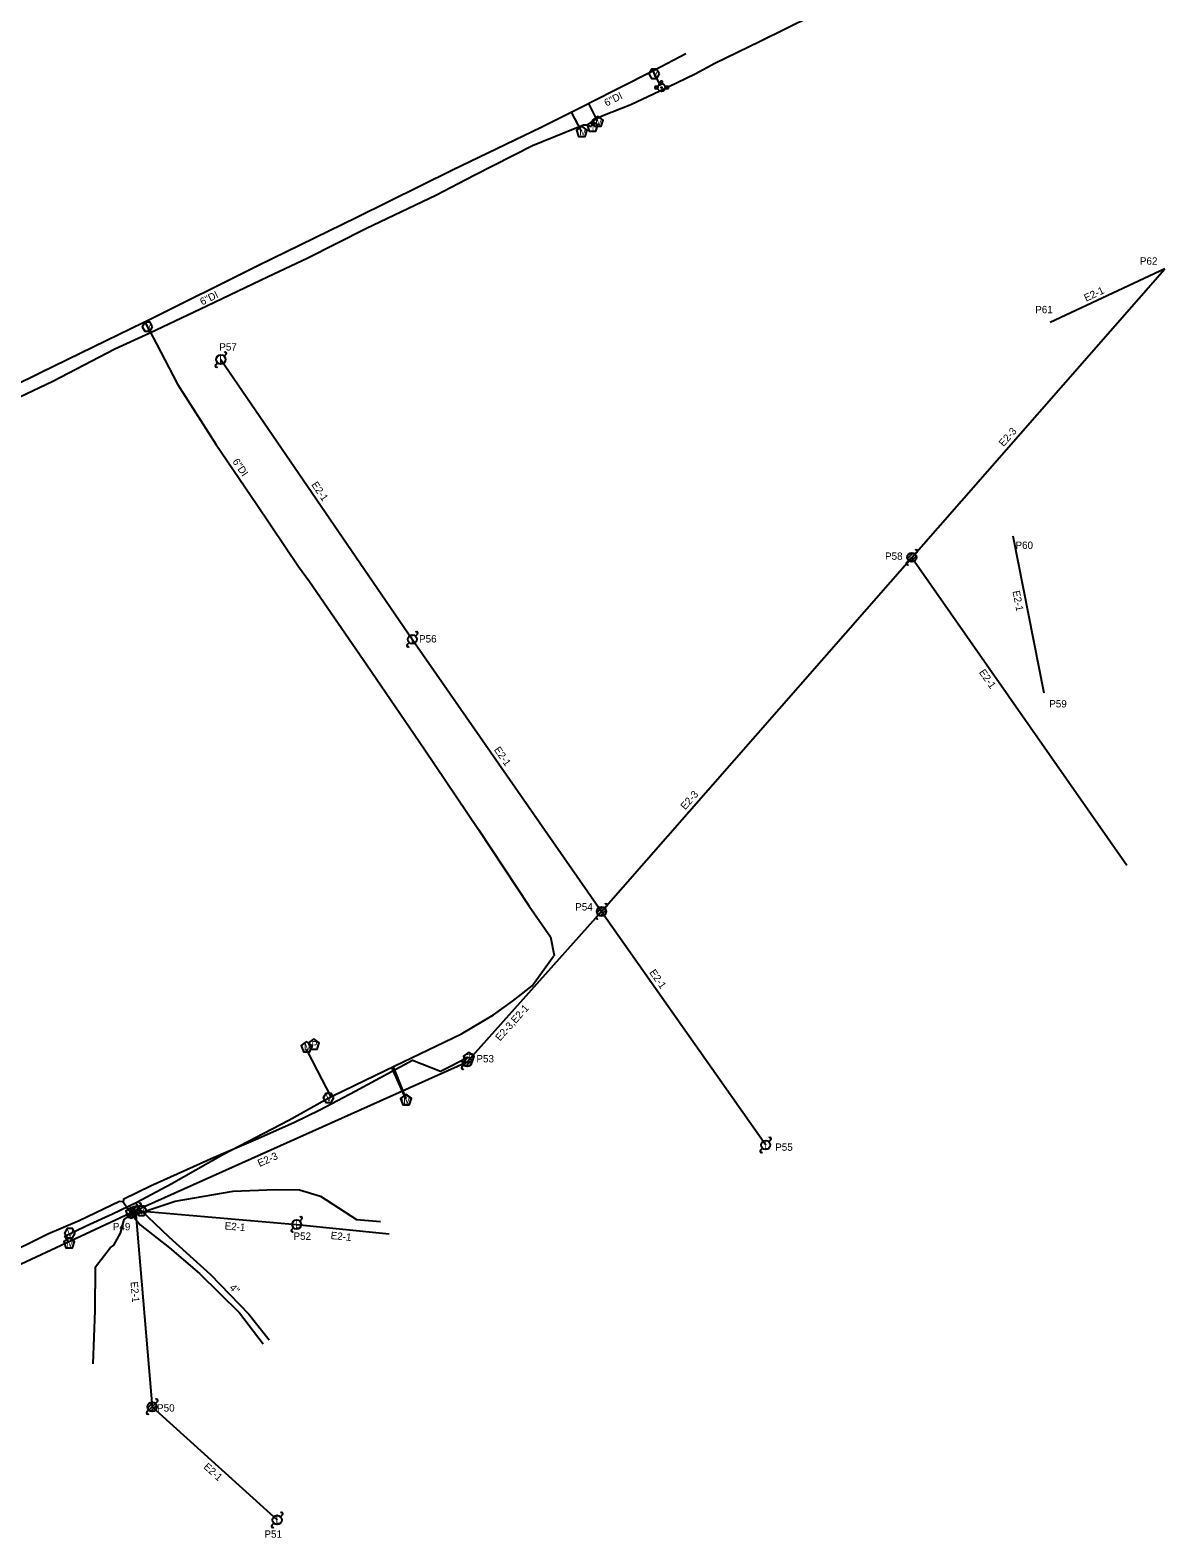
# Model space of a CAD drawing. Extents: x 1614474 to 1865144, y 1098877 to 1212550.
# Drawn here: x 1756944 to 1757561, y 1169162 to 1169980 of the extents above; entities that cross this region are included whole.
import ezdxf

# ---------------------------------------------------------------- set-up
doc = ezdxf.new("R2010")
doc.units = 0
for name, color, linetype in [('RD_EX_SU_H2O', 7, 'Continuous'), ('RD_EX_SU_Ovhd', 7, 'Continuous'), ('RD_EX_SU_Pole', 7, 'Continuous'), ('RD_EX_SU_Telecom', 7, 'Continuous'), ('RD_EX_SU_TX_H2O', 7, 'Continuous'), ('RD_EX_SU_TX_Pole', 7, 'Continuous')]:
    doc.layers.add(name, color=color, linetype=linetype)

# ---------------------------------------------------------------- blocks, each defined once
blk = doc.blocks.new('SUE_WM')
at = {"layer": 'RD_EX_SU_H2O'}
blk.add_lwpolyline([(0, 3.05), (-2.9, 0.94), (-1.79, -2.47), (1.79, -2.47), (2.9, 0.94)], close=True, dxfattribs=at)
blk.add_text('M', height=3.75, dxfattribs=at).set_placement((-1.43, -1.88))
blk = doc.blocks.new('SUE_WV')
at = {"layer": 'RD_EX_SU_H2O'}
blk.add_lwpolyline([(2.89, 0), (1.44, 2.5), (-1.44, 2.5), (-2.89, 0), (-1.44, -2.5), (1.44, -2.5)], close=True, dxfattribs=at)
blk.add_text('V', height=3.75, dxfattribs=at).set_placement((-1.43, -1.88))
blk = doc.blocks.new('SUE_TPP')
at = {"layer": 'RD_EX_SU_Telecom'}
blk.add_lwpolyline([(0, 3), (-2.85, 0.93), (-1.76, -2.43), (1.76, -2.43), (2.85, 0.93)], close=True, dxfattribs=at)
blk.add_text('T', height=3.75, dxfattribs=at).set_placement((-1.25, -1.88))

msp = doc.modelspace()

# ---------------------------------------------------------------- linework, layer by layer
at = {"layer": 'RD_EX_SU_H2O'}
for p, q in [((1757282.53, 1169958.35), (1757286.61, 1169950.33)), ((1757285.26, 1169949.92), (1757283.63, 1169949.92)), ((1757283.63, 1169949.92), (1757283.63, 1169948.87)), ((1757283.63, 1169948.87), (1757285.22, 1169948.87)), ((1757286.79, 1169952.7), (1757286.79, 1169951.36)), ((1757287.84, 1169952.7), (1757286.79, 1169952.7)), ((1757287.84, 1169951.34), (1757287.84, 1169952.7)), ((1757290.98, 1169949.92), (1757289.29, 1169949.92)), ((1757289.33, 1169948.87), (1757290.98, 1169948.87)), ((1757290.98, 1169948.87), (1757290.98, 1169949.92)), ((1757247.59, 1169940.71), (1757252.37, 1169931.3)), ((1757238.16, 1169935.97), (1757243.69, 1169925.62)), ((1757140.67, 1169417.32), (1757148.29, 1169400.22)), ((1757141.49, 1169417.71), (1757148.47, 1169400.5))]:
    msp.add_line(p, q, dxfattribs=at)
for points in [[(1756876.22, 1169758.33), (1756950.1, 1169794.65), (1756985.75, 1169811.98), (1757005.71, 1169821.7), (1757007.74, 1169822.73), (1757068.09, 1169852.64), (1757121.72, 1169879.04), (1757173.85, 1169904.73), (1757221.98, 1169927.84), (1757237.2, 1169935.44), (1757238.85, 1169936.36), (1757246.58, 1169940.19), (1757248.96, 1169941.41), (1757281.53, 1169957.91), (1757283.28, 1169958.73), (1757300.53, 1169967.83)], [(1757006.66, 1169822.19), (1757012.99, 1169810.13), (1757024.5, 1169788.2), (1757045.29, 1169755.66), (1757067.46, 1169722.91), (1757090.16, 1169689.33)], [(1757090.16, 1169689.33), (1757096.05, 1169681.09), (1757127.18, 1169635.98), (1757158.33, 1169590.22), (1757187.84, 1169546.51), (1757215.37, 1169504.84), (1757226.9, 1169488.18), (1757228.91, 1169478.06), (1757228.65, 1169477.7)], [(1756965.33, 1169322.24), (1756963.21, 1169325.73), (1756974.8, 1169331.25), (1756989.08, 1169337.78), (1757002.37, 1169344.21), (1757021, 1169354.2), (1757049.09, 1169370.07), (1757084.79, 1169388.71), (1757104.65, 1169399.79), (1757108.73, 1169401.93), (1757131.58, 1169412.99), (1757142.37, 1169418.13), (1757178.58, 1169435.66), (1757196, 1169445.83), (1757206.34, 1169453.3), (1757217.04, 1169461.72), (1757228.65, 1169477.7)], [(1757107.82, 1169401.45), (1757100.47, 1169415.66), (1757094.52, 1169427.24)], [(1757001.74, 1169343.86), (1757004.27, 1169340.03), (1757019.77, 1169325.31), (1757042.39, 1169304.84), (1757063.14, 1169283.41), (1757074.27, 1169269.39)]]:
    msp.add_lwpolyline(points, dxfattribs=at)
for points in [[(1757286.11, 1169956.75), (1757284.67, 1169959.25), (1757281.78, 1169959.25), (1757280.34, 1169956.75), (1757281.78, 1169954.25), (1757284.67, 1169954.25)], [(1757244, 1169928.34), (1757241.1, 1169926.23), (1757242.2, 1169922.82), (1757245.79, 1169922.82), (1757246.9, 1169926.23)], [(1757252.72, 1169933.8), (1757249.82, 1169931.69), (1757250.93, 1169928.28), (1757254.51, 1169928.28), (1757255.62, 1169931.69)], [(1757010.93, 1169819.47), (1757009.49, 1169821.97), (1757006.6, 1169821.97), (1757005.16, 1169819.47), (1757006.6, 1169816.97), (1757009.49, 1169816.97)], [(1757098.42, 1169432.8), (1757095.52, 1169430.69), (1757096.63, 1169427.28), (1757100.21, 1169427.28), (1757101.32, 1169430.69)]]:
    msp.add_lwpolyline(points, close=True, dxfattribs=at)
for radius in [2.1, 0.263]:
    msp.add_circle((1757287.27, 1169949.32), radius, dxfattribs=at)
for start, end in [(163.3387, 192.31502), (74.24552, 103.21276), (347.68498, 16.6613)]:
    msp.add_arc((1757287.27, 1169949.32), 2.1, start, end, dxfattribs=at)
at = {"layer": 'RD_EX_SU_Ovhd'}
for p, q in [((1757423.2, 1169694.27), (1757560.62, 1169850.85)), ((1757560.62, 1169850.85), (1757498.34, 1169821.68)), ((1757047.98, 1169801.67), (1757151.94, 1169649.78)), ((1757477.99, 1169706.01), (1757494.88, 1169620.74)), ((1757254.71, 1169502.01), (1757423.2, 1169694.27)), ((1757423.2, 1169694.27), (1757539.92, 1169527.12)), ((1757151.94, 1169649.78), (1757254.71, 1169502.01)), ((1757181.7, 1169420.4), (1757254.71, 1169502.01)), ((1757254.71, 1169502.01), (1757343.85, 1169375.24)), ((1757001.63, 1169339.59), (1757181.7, 1169420.4)), ((1756708.15, 1169203.09), (1757001.63, 1169339.59)), ((1757001.63, 1169339.59), (1757010.67, 1169233.11)), ((1757001.63, 1169339.59), (1757089.13, 1169332.08)), ((1757089.13, 1169332.08), (1757139.42, 1169327.03)), ((1757010.67, 1169233.11), (1757078.55, 1169171.67))]:
    msp.add_line(p, q, dxfattribs=at)
at = {"layer": 'RD_EX_SU_Pole'}
for p, q in [((1757045.16, 1169798.84), (1757046.22, 1169799.9)), ((1757049.75, 1169803.44), (1757050.81, 1169804.5)), ((1757420.37, 1169691.44), (1757421.43, 1169692.5)), ((1757420.79, 1169693.62), (1757423.85, 1169696.69)), ((1757421.43, 1169692.5), (1757424.97, 1169696.04)), ((1757422.55, 1169691.86), (1757425.61, 1169694.92)), ((1757424.97, 1169696.04), (1757426.03, 1169697.1)), ((1757153.7, 1169651.54), (1757154.77, 1169652.61)), ((1757149.11, 1169646.95), (1757150.17, 1169648.01)), ((1757252.29, 1169501.36), (1757255.36, 1169504.43)), ((1757252.94, 1169500.24), (1757256.48, 1169503.78)), ((1757254.06, 1169499.6), (1757257.12, 1169502.66)), ((1757256.48, 1169503.78), (1757257.54, 1169504.84)), ((1757251.88, 1169499.18), (1757252.94, 1169500.24)), ((1757179.29, 1169419.76), (1757182.36, 1169422.82)), ((1757179.94, 1169418.64), (1757183.48, 1169422.17)), ((1757181.06, 1169417.99), (1757184.12, 1169421.05)), ((1757183.48, 1169422.17), (1757184.54, 1169423.23)), ((1757178.88, 1169417.58), (1757179.94, 1169418.64)), ((1757341.02, 1169372.42), (1757342.08, 1169373.48)), ((1757345.61, 1169377.01), (1757346.67, 1169378.07)), ((1756999.22, 1169338.94), (1757002.28, 1169342)), ((1756999.87, 1169337.82), (1757003.4, 1169341.35)), ((1757000.99, 1169337.17), (1757004.05, 1169340.23)), ((1757003.4, 1169341.35), (1757004.46, 1169342.41)), ((1756998.8, 1169336.76), (1756999.87, 1169337.82)), ((1757090.89, 1169333.85), (1757091.95, 1169334.91)), ((1757086.3, 1169329.25), (1757087.36, 1169330.31)), ((1757008.25, 1169232.46), (1757011.31, 1169235.52)), ((1757008.9, 1169231.34), (1757012.43, 1169234.87)), ((1757010.02, 1169230.69), (1757013.08, 1169233.75)), ((1757012.43, 1169234.87), (1757013.49, 1169235.94)), ((1757007.84, 1169230.28), (1757008.9, 1169231.34)), ((1757075.72, 1169168.84), (1757076.78, 1169169.9)), ((1757080.32, 1169173.44), (1757081.38, 1169174.5))]:
    msp.add_line(p, q, dxfattribs=at)
for centre in [(1757047.98, 1169801.67), (1757423.2, 1169694.27), (1757151.94, 1169649.78), (1757254.71, 1169502.01), (1757181.71, 1169420.4), (1757343.85, 1169375.24), (1757001.63, 1169339.59), (1757089.13, 1169332.08), (1757010.67, 1169233.11), (1757078.55, 1169171.67)]:
    msp.add_circle(centre, 2.5, dxfattribs=at)
for centre, start, end in [((1757050.28, 1169805.03), 315, 135), ((1757045.69, 1169798.31), 135, 315), ((1757420.9, 1169690.91), 135, 315), ((1757425.5, 1169697.63), 315, 135), ((1757154.24, 1169653.14), 315, 135), ((1757149.64, 1169646.42), 135, 315), ((1757257.01, 1169505.37), 315, 135), ((1757252.41, 1169498.65), 135, 315), ((1757184.01, 1169423.76), 315, 135), ((1757179.41, 1169417.05), 135, 315), ((1757341.55, 1169371.89), 135, 315), ((1757346.14, 1169378.6), 315, 135), ((1757003.93, 1169342.95), 315, 135), ((1756999.33, 1169336.23), 135, 315), ((1757091.42, 1169335.44), 315, 135), ((1757086.83, 1169328.72), 135, 315), ((1757012.96, 1169236.47), 315, 135), ((1757008.37, 1169229.75), 135, 315), ((1757080.85, 1169175.03), 315, 135), ((1757076.25, 1169168.31), 135, 315)]:
    msp.add_arc(centre, 0.75, start, end, dxfattribs=at)
at = {"layer": 'RD_EX_SU_Telecom'}
for points in [[(1757249.55, 1169928.45), (1757249.88, 1169931.2), (1757255.33, 1169934.08), (1757270.6, 1169940.16), (1757286.37, 1169947.59), (1757305.48, 1169956.83), (1757316.21, 1169962.48), (1757340.76, 1169974.57), (1757368.73, 1169988.17), (1757389.1, 1169999.22), (1757392.59, 1169999.03)], [(1756931.59, 1169777.98), (1756956.76, 1169789.88), (1756990.34, 1169807.49), (1757009.39, 1169816.23), (1757040.27, 1169830.82), (1757073.64, 1169846.73), (1757094.85, 1169856.73), (1757127, 1169873.01), (1757164.77, 1169890.84), (1757185.55, 1169901.74), (1757217.23, 1169917.77), (1757235.48, 1169925.34), (1757244.86, 1169929.08), (1757246.7, 1169929.13), (1757249.31, 1169928.24)], [(1756995.17, 1169343.88), (1756995.27, 1169346.03), (1757009.75, 1169353.03), (1757043.89, 1169368.52), (1757068, 1169378.78), (1757087.87, 1169387.6), (1757101.69, 1169394.24), (1757120.91, 1169404.43), (1757151.98, 1169421.3), (1757167.24, 1169415.35), (1757181.92, 1169422.71)], [(1756999.66, 1169337.88), (1757004.2, 1169338.44), (1757023.23, 1169344.64), (1757054.7, 1169350.16), (1757077.42, 1169351.12), (1757090.71, 1169350.92), (1757102.01, 1169347.48), (1757121.7, 1169334.78), (1757134.68, 1169333.63)], [(1756706.93, 1169203.78), (1756705.63, 1169208.7), (1756739.31, 1169225.47), (1756751.07, 1169231.4), (1756775.8, 1169242.36), (1756801.58, 1169252.27), (1756827.44, 1169264.14), (1756856.35, 1169277.94), (1756883.6, 1169291.76), (1756909.38, 1169304.26), (1756928.56, 1169314.26), (1756954.07, 1169326.93), (1756971.08, 1169334.18), (1756992.88, 1169344.76), (1756994.71, 1169344.5), (1756998.78, 1169338.96)], [(1756978.66, 1169256.46), (1756979.64, 1169285.32), (1756979.91, 1169309.12), (1756987.8, 1169319.34), (1756989.93, 1169320.81), (1756993.47, 1169327.28), (1756995.47, 1169334.76), (1756997.44, 1169336.29), (1756998.65, 1169338.15)], [(1756999.02, 1169338.03), (1757004.1, 1169331.95), (1757020.11, 1169319.4), (1757036.37, 1169305.42), (1757058.04, 1169284.15), (1757070.99, 1169267.33)]]:
    msp.add_lwpolyline(points, dxfattribs=at)
msp.add_lwpolyline([(1757249.76, 1169931.16), (1757246.91, 1169929.09), (1757248, 1169925.73), (1757251.53, 1169925.73), (1757252.62, 1169929.09)], close=True, dxfattribs=at)

# ---------------------------------------------------------------- block references
at = {"layer": 'RD_EX_SU_H2O'}
for name, p in [('SUE_WM', (1757094.55, 1169428.32)), ('SUE_WV', (1757106.42, 1169400.75)), ('SUE_WM', (1757148.51, 1169399.56)), ('SUE_WM', (1757148.59, 1169399.72)), ('SUE_WV', (1757004.81, 1169339.53)), ('SUE_WM', (1756965.55, 1169321.81)), ('SUE_WV', (1756965.93, 1169327.31))]:
    msp.add_blockref(name, p, dxfattribs=at)
at = {"layer": 'RD_EX_SU_Telecom'}
for p in [(1757182.66, 1169422.55), (1756999.25, 1169338.55)]:
    msp.add_blockref('SUE_TPP', p, dxfattribs=at)

# ---------------------------------------------------------------- texts
at = {"layer": 'RD_EX_SU_H2O'}
for s, p in [('V', (1757282.01, 1169954.88)), ('M', (1757251.35, 1169928.76)), ('M', (1757242.63, 1169923.3)), ('V', (1757006.84, 1169817.59)), ('P', (1757097.17, 1169427.87))]:
    msp.add_text(s, height=3.75, dxfattribs=at).set_placement(p)
at = {"layer": 'RD_EX_SU_Ovhd'}
for s, rotation, p in [('E2-1', 25.09315, (1757517.86, 1169833.03)), ('E2-3', 48.72781, (1757473.02, 1169754.07)), ('E2-1', 304.38663, (1757096.93, 1169733.69)), ('E2-1', 281.20124, (1757477.85, 1169675.83)), ('E2-1', 304.92553, (1757459.49, 1169631.81)), ('E2-1', 304.8191, (1757196.1, 1169589.78)), ('E2-3', 48.76969, (1757300.14, 1169556.89)), ('E2-1', 305.11281, (1757280.46, 1169468.86)), ('E2-3,E2-1', 48.18166, (1757199.55, 1169431.36)), ('E2-3', 24.17169, (1757069.01, 1169363.25)), ('E2-1', 355.09573, (1757049.88, 1169329.42)), ('E2-1', 354.26572, (1757107.45, 1169324.21)), ('E2-1', 274.84928, (1756998.89, 1169300.89)), ('E2-1', 317.85308, (1757038.25, 1169200.05))]:
    msp.add_text(s, height=4, rotation=rotation, dxfattribs=at).set_placement(p)
at = {"layer": 'RD_EX_SU_Pole'}
for p in [(1757047.12, 1169799.67), (1757151.07, 1169647.78), (1757342.98, 1169373.24), (1757088.26, 1169330.08), (1757077.69, 1169169.67)]:
    msp.add_text('L', height=4, dxfattribs=at).set_placement(p)
at = {"layer": 'RD_EX_SU_Telecom'}
msp.add_text('T', height=3.75, dxfattribs=at).set_placement((1757248.53, 1169925.93))
at = {"layer": 'RD_EX_SU_TX_H2O'}
for s, rotation, p in [('6"DI', 26.86965, (1757257.4, 1169938.95)), ('6"DI', 26.35764, (1757037.85, 1169830.96)), ('6"DI', 304.0968, (1757054.08, 1169746.24)), ('4"', 314.08328, (1757052.33, 1169297.45))]:
    msp.add_text(s, height=4, rotation=rotation, dxfattribs=at).set_placement(p)
at = {"layer": 'RD_EX_SU_TX_Pole'}
for s, p in [('P62', (1757547.07, 1169853.14)), ('P61', (1757490.22, 1169826.79)), ('P57', (1757047.11, 1169806.54)), ('P60', (1757479.51, 1169698.84)), ('P58', (1757408.67, 1169692.93)), ('P56', (1757155.62, 1169648.03)), ('P59', (1757497.84, 1169612.79)), ('P54', (1757240.41, 1169502.52)), ('P53', (1757186.76, 1169420.06)), ('P55', (1757349.02, 1169372.08)), ('P49', (1756989.3, 1169328.92)), ('P52', (1757087.42, 1169323.73)), ('P50', (1757013.34, 1169230.48)), ('P51', (1757071.64, 1169162))]:
    msp.add_text(s, height=4, dxfattribs=at).set_placement(p)

doc.saveas('drawing.dxf')
